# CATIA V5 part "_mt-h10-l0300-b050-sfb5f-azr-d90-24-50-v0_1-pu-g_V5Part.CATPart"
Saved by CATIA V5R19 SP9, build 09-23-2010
Part number: _mt-h10-l0300-b050-sfb5f-azr-d90-24-50-v0_1-pu-g_V5Part
Bounding box of the stored display mesh (mm): x -63 to 78, y -174.5 to 7.2, z -306.5 to 80.1
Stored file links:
  D:\#work\TMP\_mt-h10-l0300-b050-sfb5f-azr-d90-24-50-v0_1-pu-g_V5Part.CATPart
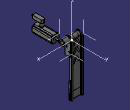
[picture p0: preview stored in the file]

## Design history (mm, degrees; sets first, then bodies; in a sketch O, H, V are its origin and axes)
AxisSystem1: origin (0, 0, 0), X (1, 0, 0), Y (0, 1, 0), Z (0, 0, 1)
Body1 "PartBody ( *SOL34 - wsp *MASTER -  -Non Smart-  )" (main body)
  Solid1 "Solid.1 (  with JELE 13872 : from  with JELE 13872 - wsp *MASTER -  ) ( Brep from *SOL34 )": solid without history
Body2 "Body.2 ( *SOL33 - wsp *MASTER -  -Non Smart-  )"
  Solid2 "Solid.2 (  with JELE 13712 : from  with JELE 13712 - wsp *MASTER -  ) ( Brep from *SOL33 )": solid without history
Body3 "Body.3 ( *SOL32 - wsp *MASTER -  -Non Smart-  )"
  Solid3 "Solid.3 (  with JELE 12630 : from  with JELE 12630 - wsp *MASTER -  ) ( Brep from *SOL32 )": solid without history
Body4 "Body.4 ( *SOL31 - wsp *MASTER -  -Non Smart-  _with_error_during_paste )"
Body5 "Body.5 ( *SOL30 - wsp *MASTER -  -Non Smart-  )"
  Solid4 "Solid.4 (  with JELE 11544 : from  with JELE 11544 - wsp *MASTER -  ) ( Brep from *SOL30 )": solid without history
Body6 "Body.6 ( *SOL29 - wsp *MASTER -  -Non Smart-  )"
  Solid5 "Solid.5 (  with JELE 11310 : from  with JELE 11310 - wsp *MASTER -  ) ( Brep from *SOL29 )": solid without history
Body7 "Body.7 ( *SOL28 - wsp *MASTER -  -Non Smart-  )"
  Solid6 "Solid.6 (  with JELE 11276 : from  with JELE 11276 - wsp *MASTER -  ) ( Brep from *SOL28 )": solid without history
Body8 "Body.8 ( *SOL27 - wsp *MASTER -  -Non Smart-  )"
  Solid7 "Solid.7 (  with JELE 11202 : from  with JELE 11202 - wsp *MASTER -  ) ( Brep from *SOL27 )": solid without history
Body9 "Body.9 ( *SOL26 - wsp *MASTER -  -Non Smart-  )"
  Solid8 "Solid.8 (  with JELE 11128 : from  with JELE 11128 - wsp *MASTER -  ) ( Brep from *SOL26 )": solid without history
Body10 "Body.10 ( *SOL25 - wsp *MASTER -  -Non Smart-  )"
  Solid9 "Solid.9 (  with JELE 10464 : from  with JELE 10464 - wsp *MASTER -  ) ( Brep from *SOL25 )": solid without history
Body11 "Body.11 ( *SOL24 - wsp *MASTER -  -Non Smart-  )"
  Solid10 "Solid.10 (  with JELE 10280 : from  with JELE 10280 - wsp *MASTER -  ) ( Brep from *SOL24 )": solid without history
Body12 "Body.12 ( *SOL23 - wsp *MASTER -  -Non Smart-  )"
  Solid11 "Solid.11 (  with JELE 10216 : from  with JELE 10216 - wsp *MASTER -  ) ( Brep from *SOL23 )": solid without history
Body13 "Body.13 ( *SOL22 - wsp *MASTER -  -Non Smart-  )"
  Solid12 "Solid.12 (  with JELE 10152 : from  with JELE 10152 - wsp *MASTER -  ) ( Brep from *SOL22 )": solid without history
Body14 "Body.14 ( *SOL21 - wsp *MASTER -  -Non Smart-  )"
  Solid13 "Solid.13 (  with JELE 10060 : from  with JELE 10060 - wsp *MASTER -  ) ( Brep from *SOL21 )": solid without history
Body15 "Body.15 ( *SOL20 - wsp *MASTER -  -Non Smart-  )"
  Solid14 "Solid.14 (  with JELE 10026 : from  with JELE 10026 - wsp *MASTER -  ) ( Brep from *SOL20 )": solid without history
Body16 "Body.16 ( *SOL19 - wsp *MASTER -  -Non Smart-  )"
  Solid15 "Solid.15 (  with JELE 9952 : from  with JELE 9952 - wsp *MASTER -  ) ( Brep from *SOL19 )": solid without history
Body17 "Body.17 ( *SOL18 - wsp *MASTER -  -Non Smart-  )"
  Solid16 "Solid.16 (  with JELE 9834 : from  with JELE 9834 - wsp *MASTER -  ) ( Brep from *SOL18 )": solid without history
Body18 "Body.18 ( *SOL17 - wsp *MASTER -  -Non Smart-  )"
  Solid17 "Solid.17 (  with JELE 9096 : from  with JELE 9096 - wsp *MASTER -  ) ( Brep from *SOL17 )": solid without history
Body19 "Body.19 ( *SOL16 - wsp *MASTER -  -Non Smart-  )"
  Solid18 "Solid.18 (  with JELE 9032 : from  with JELE 9032 - wsp *MASTER -  ) ( Brep from *SOL16 )": solid without history
Body20 "Body.20 ( *SOL15 - wsp *MASTER -  -Non Smart-  )"
  Solid19 "Solid.19 (  with JELE 8968 : from  with JELE 8968 - wsp *MASTER -  ) ( Brep from *SOL15 )": solid without history
Body21 "Body.21 ( *SOL14 - wsp *MASTER -  -Non Smart-  )"
  Solid20 "Solid.20 (  with JELE 8894 : from  with JELE 8894 - wsp *MASTER -  ) ( Brep from *SOL14 )": solid without history
Body22 "Body.22 ( *SOL13 - wsp *MASTER -  -Non Smart-  )"
  Solid21 "Solid.21 (  with JELE 8742 : from  with JELE 8742 - wsp *MASTER -  ) ( Brep from *SOL13 )": solid without history
Body23 "Body.23 ( *SOL12 - wsp *MASTER -  -Non Smart-  )"
  Solid22 "Solid.22 (  with JELE 8708 : from  with JELE 8708 - wsp *MASTER -  ) ( Brep from *SOL12 )": solid without history
Body24 "Body.24 ( *SOL11 - wsp *MASTER -  -Non Smart-  )"
  Solid23 "Solid.23 (  with JELE 8474 : from  with JELE 8474 - wsp *MASTER -  ) ( Brep from *SOL11 )": solid without history
Body25 "Body.25 ( *SOL10 - wsp *MASTER -  -Non Smart-  )"
  Solid24 "Solid.24 (  with JELE 8400 : from  with JELE 8400 - wsp *MASTER -  ) ( Brep from *SOL10 )": solid without history
Body26 "Body.26 ( *SOL9 - wsp *MASTER -  -Non Smart-  )"
  Solid25 "Solid.25 (  with JELE 8326 : from  with JELE 8326 - wsp *MASTER -  ) ( Brep from *SOL9 )": solid without history
Body27 "Body.27 ( *SOL8 - wsp *MASTER -  -Non Smart-  )"
  Solid26 "Solid.26 (  with JELE 7910 : from  with JELE 7910 - wsp *MASTER -  ) ( Brep from *SOL8 )": solid without history
Body28 "Body.28 ( *SOL7 - wsp *MASTER -  -Non Smart-  )"
  Solid27 "Solid.27 (  with JELE 7876 : from  with JELE 7876 - wsp *MASTER -  ) ( Brep from *SOL7 )": solid without history
Body29 "Body.29 ( *SOL6 - wsp *MASTER -  -Non Smart-  )"
  Solid28 "Solid.28 (  with JELE 7802 : from  with JELE 7802 - wsp *MASTER -  ) ( Brep from *SOL6 )": solid without history
Body30 "Body.30 ( *SOL5 - wsp *MASTER -  -Non Smart-  )"
  Solid29 "Solid.29 (  with JELE 7728 : from  with JELE 7728 - wsp *MASTER -  ) ( Brep from *SOL5 )": solid without history
Body31 "Body.31 ( *SOL4 - wsp *MASTER -  -Non Smart-  )"
  Solid30 "Solid.30 (  with JELE 7312 : from  with JELE 7312 - wsp *MASTER -  ) ( Brep from *SOL4 )": solid without history
Body32 "Body.32 ( *SOL3 - wsp *MASTER -  -Non Smart-  )"
  Solid31 "Solid.31 (  with JELE 7278 : from  with JELE 7278 - wsp *MASTER -  ) ( Brep from *SOL3 )": solid without history
Body33 "Body.33 ( *SOL2 - wsp *MASTER -  -Non Smart-  )"
  Solid32 "Solid.32 (  with JELE 6528 : from  with JELE 6528 - wsp *MASTER -  ) ( Brep from *SOL2 )": solid without history
Body34 "Body.34 ( *SOL1 - wsp *MASTER -  -Non Smart-  )"
  Solid33 "Solid.33 (  with JELE 5850 : from *SOL1 - wsp *MASTER -  ) ( Brep from *SOL1 )": solid without history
